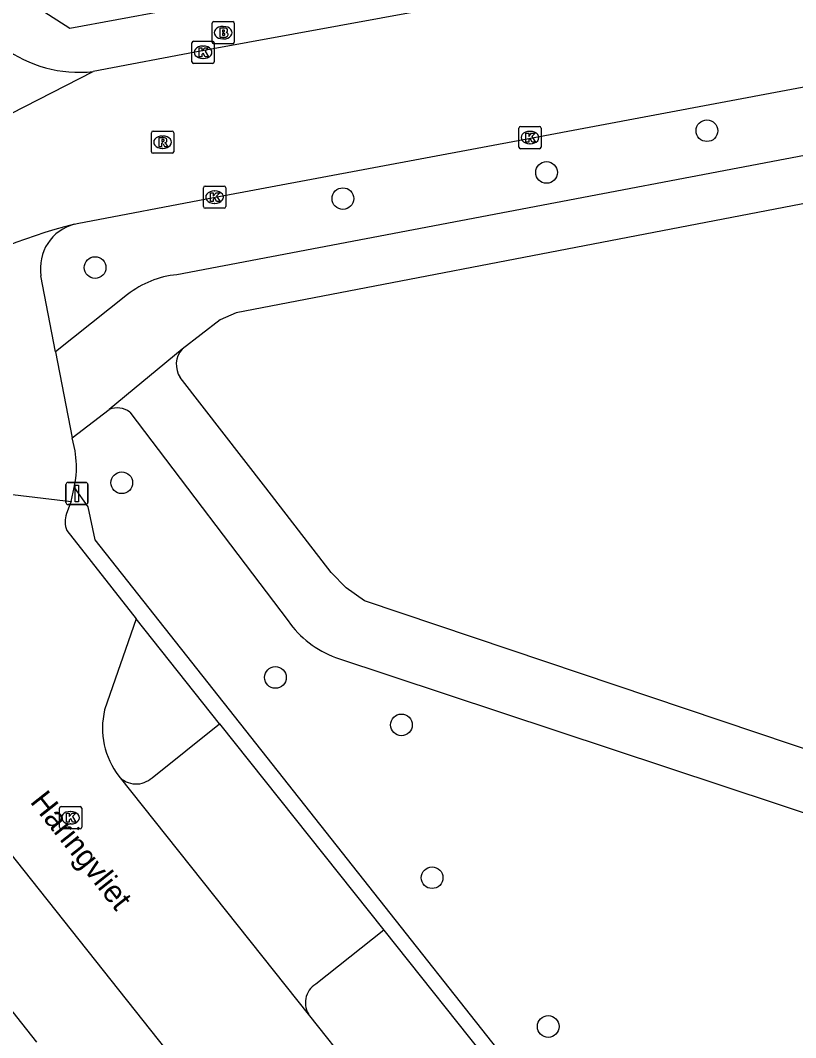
# Model space of a CAD drawing. Extents: x 157321 to 158827, y 386650 to 388532.
# Drawn here: x 157800.78 to 157835.71, y 387550.03 to 387595.87 of the extents above; entities that cross this region are included whole.
import ezdxf

# ---------------------------------------------------------------- set-up
doc = ezdxf.new("R2010")
doc.units = 0
for name, color, linetype in [('IMGEO_Boom', 7, 'Continuous'), ('IMGEO_Brandkraan', 7, 'Continuous'), ('IMGEO_Fietspad_open', 7, 'Continuous'), ('IMGEO_Haag', 7, 'Continuous'), ('IMGEO_Kolk', 7, 'Continuous'), ('IMGEO_Openbare_ruimte_label', 7, 'Continuous'), ('IMGEO_Pand', 7, 'Continuous'), ('IMGEO_Parkeervlak_open', 7, 'Continuous'), ('IMGEO_Rijbaan_lokaal_open', 7, 'Continuous'), ('IMGEO_Rioolput', 7, 'Continuous'), ('IMGEO_Verkeersbordpaal', 7, 'Continuous'), ('IMGEO_Voetpad_open', 7, 'Continuous')]:
    doc.layers.add(name, color=color, linetype=linetype)

msp = doc.modelspace()

# ---------------------------------------------------------------- linework, layer by layer
at = {"layer": 'IMGEO_Boom'}
for centre in [(157831.711, 387590.895), (157824.484, 387589.013), (157815.311, 387587.834), (157804.146, 387584.726), (157805.348, 387575.035), (157812.269, 387566.26), (157817.946, 387564.122), (157819.328, 387557.239), (157824.561, 387550.534)]:
    msp.add_circle(centre, 0.489, dxfattribs=at)
at = {"layer": 'IMGEO_Brandkraan'}
for p, q in [((157809.418, 387594.886), (157809.418, 387595.738)), ((157809.493, 387595.812), (157810.345, 387595.812)), ((157809.906, 387595.592), (157809.931, 387595.592)), ((157810.419, 387595.738), (157810.419, 387594.886)), ((157809.929, 387595.032), (157809.904, 387595.032)), ((157810.345, 387594.812), (157809.493, 387594.812))]:
    msp.add_line(p, q, dxfattribs=at)
for points in [[(157809.418, 387594.886), (157809.418, 387595.738)], [(157809.493, 387595.812), (157810.345, 387595.812)], [(157809.766, 387595.512), (157809.766, 387595.112), (157809.979, 387595.112)], [(157809.997, 387595.512), (157809.766, 387595.512)], [(157810.419, 387595.738), (157810.419, 387594.886)], [(157809.945, 387595.431), (157809.891, 387595.431), (157809.891, 387595.355)], [(157809.891, 387595.355), (157809.944, 387595.355)], [(157809.953, 387595.279), (157809.891, 387595.279), (157809.891, 387595.198)], [(157809.891, 387595.198), (157809.953, 387595.198)], [(157810.345, 387594.812), (157809.493, 387594.812)]]:
    msp.add_lwpolyline(points, dxfattribs=at)
for centre, radius, start, end in [((157809.495, 387595.736), 0.0765, 91.552, 178.448), ((157809.495, 387595.736), 0.0765, 91.552, 178.448), ((157810.001, 387595.367), 0.145, 59.4692, 91.5367), ((157810.026, 387595.414), 0.0922, 285.5137, 58.1501), ((157810.343, 387595.736), 0.0765, 1.552, 88.448), ((157810.343, 387595.736), 0.0765, 1.552, 88.448), ((157809.946, 387595.393), 0.0379, 267.8285, 90.9355), ((157809.954, 387595.238), 0.0404, 269.8759, 90.5077), ((157809.985, 387595.363), 0.251, 268.6676, 293.5347), ((157810.031, 387595.222), 0.105, 301.3115, 78.989), ((157809.495, 387594.888), 0.0765, 181.552, 268.448), ((157809.495, 387594.888), 0.0765, 181.552, 268.448), ((157810.343, 387594.888), 0.0765, 271.552, 358.448), ((157810.343, 387594.888), 0.0765, 271.552, 358.448)]:
    msp.add_arc(centre, radius, start, end, dxfattribs=at)
for centre, major_axis, ratio, start_param, end_param in [((157809.905, 387595.312), (-0.387, 0.002), 0.722429, 4.712389, 7.853982), ((157809.93, 387595.312), (-0.39, 0.002), 0.717154, 1.570796, 4.712389)]:
    msp.add_ellipse(centre, major_axis=major_axis, ratio=ratio, start_param=start_param, end_param=end_param, dxfattribs=at)
at = {"layer": 'IMGEO_Fietspad_open'}
for points in [[(157802.364, 387580.934), (157801.707, 387584.358)], [(157802.364, 387580.934), (157803.109, 387577.055)], [(157803.247, 387576.474), (157803.109, 387577.055)], [(157803.067, 387574.191), (157803.21, 387574.813)], [(157803.21, 387574.813), (157803.282, 387575.231)]]:
    msp.add_lwpolyline(points, dxfattribs=at)
for centre, radius, start, end in [((157803.747, 387584.69), 2.067, 104.6294, 189.2469), ((157798.269, 387575.712), 5.036, 354.5212, 8.7046)]:
    msp.add_arc(centre, radius, start, end, dxfattribs=at)
at = {"layer": 'IMGEO_Haag'}
for points in [[(157803.21, 387574.813), (157803.815, 387573.954), (157804.139, 387572.463), (157834.85, 387533.597)], [(157809.751, 387564.168), (157805.996, 387568.908)], [(157817.15, 387554.871), (157822.119, 387548.629)]]:
    msp.add_lwpolyline(points, dxfattribs=at)
at = {"layer": 'IMGEO_Kolk'}
for p, q in [((157808.51, 387594.002), (157808.51, 387594.854)), ((157808.585, 387594.928), (157809.437, 387594.928)), ((157808.998, 387594.708), (157809.023, 387594.708)), ((157809.511, 387594.854), (157809.511, 387594.002)), ((157809.021, 387594.148), (157808.996, 387594.148)), ((157809.437, 387593.928), (157808.585, 387593.928)), ((157823.237, 387590.158), (157823.237, 387591.01)), ((157823.312, 387591.084), (157824.164, 387591.084)), ((157823.725, 387590.864), (157823.75, 387590.864)), ((157824.238, 387591.01), (157824.238, 387590.158)), ((157824.164, 387590.084), (157823.312, 387590.084)), ((157823.748, 387590.304), (157823.723, 387590.304)), ((157809.029, 387587.475), (157809.029, 387588.327)), ((157809.104, 387588.401), (157809.956, 387588.401)), ((157809.517, 387588.181), (157809.542, 387588.181)), ((157810.03, 387588.327), (157810.03, 387587.475)), ((157809.956, 387587.401), (157809.104, 387587.401)), ((157809.54, 387587.621), (157809.515, 387587.621)), ((157802.541, 387559.514), (157802.541, 387560.366)), ((157802.616, 387560.44), (157803.468, 387560.44)), ((157803.029, 387560.22), (157803.054, 387560.22)), ((157803.542, 387560.366), (157803.542, 387559.514)), ((157803.468, 387559.44), (157802.616, 387559.44)), ((157803.052, 387559.66), (157803.027, 387559.66))]:
    msp.add_line(p, q, dxfattribs=at)
for points in [[(157808.51, 387594.002), (157808.51, 387594.854)], [(157808.585, 387594.928), (157809.437, 387594.928)], [(157808.831, 387594.628), (157808.954, 387594.628), (157808.954, 387594.477), (157809.084, 387594.628), (157809.248, 387594.628), (157809.102, 387594.477), (157809.255, 387594.228), (157809.103, 387594.228), (157809.018, 387594.392), (157808.954, 387594.325), (157808.954, 387594.228), (157808.831, 387594.228), (157808.831, 387594.628)], [(157809.511, 387594.854), (157809.511, 387594.002)], [(157809.437, 387593.928), (157808.585, 387593.928)], [(157823.237, 387590.158), (157823.237, 387591.01)], [(157823.312, 387591.084), (157824.164, 387591.084)], [(157824.238, 387591.01), (157824.238, 387590.158)], [(157823.558, 387590.784), (157823.681, 387590.784), (157823.681, 387590.633), (157823.811, 387590.784), (157823.975, 387590.784), (157823.829, 387590.633), (157823.982, 387590.384), (157823.83, 387590.384), (157823.745, 387590.548), (157823.681, 387590.481), (157823.681, 387590.384), (157823.558, 387590.384), (157823.558, 387590.784)], [(157824.164, 387590.084), (157823.312, 387590.084)], [(157809.029, 387587.475), (157809.029, 387588.327)], [(157809.104, 387588.401), (157809.956, 387588.401)], [(157810.03, 387588.327), (157810.03, 387587.475)], [(157809.35, 387588.101), (157809.473, 387588.101), (157809.473, 387587.95), (157809.603, 387588.101), (157809.767, 387588.101), (157809.621, 387587.95), (157809.774, 387587.701), (157809.622, 387587.701), (157809.537, 387587.865), (157809.473, 387587.798), (157809.473, 387587.701), (157809.35, 387587.701), (157809.35, 387588.101)], [(157809.956, 387587.401), (157809.104, 387587.401)], [(157802.541, 387559.514), (157802.541, 387560.366)], [(157802.616, 387560.44), (157803.468, 387560.44)], [(157803.542, 387560.366), (157803.542, 387559.514)], [(157802.862, 387560.14), (157802.985, 387560.14), (157802.985, 387559.989), (157803.115, 387560.14), (157803.279, 387560.14), (157803.133, 387559.989), (157803.286, 387559.74), (157803.134, 387559.74), (157803.049, 387559.904), (157802.985, 387559.837), (157802.985, 387559.74), (157802.862, 387559.74), (157802.862, 387560.14)], [(157803.468, 387559.44), (157802.616, 387559.44)]]:
    msp.add_lwpolyline(points, dxfattribs=at)
for centre, start, end in [((157808.587, 387594.852), 91.552, 178.448), ((157808.587, 387594.852), 91.552, 178.448), ((157809.435, 387594.852), 1.552, 88.448), ((157809.435, 387594.852), 1.552, 88.448), ((157808.587, 387594.004), 181.552, 268.448), ((157808.587, 387594.004), 181.552, 268.448), ((157809.435, 387594.004), 271.552, 358.448), ((157809.435, 387594.004), 271.552, 358.448), ((157823.314, 387591.008), 91.552, 178.448), ((157823.314, 387591.008), 91.552, 178.448), ((157824.162, 387591.008), 1.552, 88.448), ((157824.162, 387591.008), 1.552, 88.448), ((157823.314, 387590.16), 181.552, 268.448), ((157823.314, 387590.16), 181.552, 268.448), ((157824.162, 387590.16), 271.552, 358.448), ((157824.162, 387590.16), 271.552, 358.448), ((157809.106, 387588.325), 91.552, 178.448), ((157809.106, 387588.325), 91.552, 178.448), ((157809.954, 387588.325), 1.552, 88.448), ((157809.954, 387588.325), 1.552, 88.448), ((157809.106, 387587.477), 181.552, 268.448), ((157809.106, 387587.477), 181.552, 268.448), ((157809.954, 387587.477), 271.552, 358.448), ((157809.954, 387587.477), 271.552, 358.448), ((157802.618, 387560.364), 91.552, 178.448), ((157802.618, 387560.364), 91.552, 178.448), ((157803.466, 387560.364), 1.552, 88.448), ((157803.466, 387560.364), 1.552, 88.448), ((157802.618, 387559.516), 181.552, 268.448), ((157802.618, 387559.516), 181.552, 268.448), ((157803.466, 387559.516), 271.552, 358.448), ((157803.466, 387559.516), 271.552, 358.448)]:
    msp.add_arc(centre, 0.0765, start, end, dxfattribs=at)
for centre, major_axis, ratio, start_param, end_param in [((157808.997, 387594.428), (-0.387, 0.002), 0.722429, 4.712389, 7.853982), ((157809.022, 387594.428), (-0.39, 0.002), 0.717154, 1.570796, 4.712389), ((157823.724, 387590.584), (-0.387, 0.002), 0.722429, 4.712389, 7.853982), ((157823.749, 387590.584), (-0.39, 0.002), 0.717154, 1.570796, 4.712389), ((157809.516, 387587.901), (-0.387, 0.002), 0.722429, 4.712389, 7.853982), ((157809.541, 387587.901), (-0.39, 0.002), 0.717154, 1.570796, 4.712389), ((157803.028, 387559.94), (-0.387, 0.002), 0.722429, 4.712389, 7.853982), ((157803.053, 387559.94), (-0.39, 0.002), 0.717154, 1.570796, 4.712389)]:
    msp.add_ellipse(centre, major_axis=major_axis, ratio=ratio, start_param=start_param, end_param=end_param, dxfattribs=at)
at = {"layer": 'IMGEO_Pand'}
msp.add_lwpolyline([(157797.776, 387554.523), (157801.506, 387549.824)], dxfattribs=at)
at = {"layer": 'IMGEO_Parkeervlak_open'}
for points in [[(157806.713, 387561.742), (157809.751, 387564.168)], [(157809.751, 387564.168), (157817.15, 387554.871)], [(157817.15, 387554.871), (157814.089, 387552.441)]]:
    msp.add_lwpolyline(points, dxfattribs=at)
for centre, radius, start, end in [((157805.998, 387562.51), 1.049, 221.8551, 312.9398), ((157814.6, 387551.602), 0.982, 121.3478, 216.4662)]:
    msp.add_arc(centre, radius, start, end, dxfattribs=at)
at = {"layer": 'IMGEO_Rijbaan_lokaal_open'}
for points in [[(157847.531, 387601.774), (157838.502, 387600.061), (157823.212, 387597.114), (157808.967, 387594.489), (157804.065, 387593.562)], [(157803.225, 387586.69), (157803.34, 387586.71), (157809.483, 387587.888), (157823.694, 387590.55), (157837.996, 387593.239), (157850.039, 387595.554), (157853.29, 387595.423), (157855.571, 387595.37)], [(157792.988, 387587.904), (157804.065, 387593.562)], [(157800.167, 387574.541), (157803.067, 387574.191)], [(157803.067, 387574.191), (157803.031, 387574.082), (157802.855, 387573.642)], [(157802.873, 387572.88), (157805.996, 387568.908)], [(157805.996, 387568.908), (157804.575, 387564.795)], [(157829.287, 387521.854), (157827.412, 387524.212), (157792.348, 387568.39)], [(157805.217, 387561.81), (157813.81, 387551.018)], [(157813.81, 387551.018), (157817.616, 387546.205)]]:
    msp.add_lwpolyline(points, dxfattribs=at)
for centre, radius, start, end in [((157803.438, 387599.315), 5.787, 191.6206, 276.2197), ((157809.551, 387562.076), 25.414, 104.4143, 121.1402), ((157803.897, 387573.285), 1.102, 161.1115, 201.5949), ((157808.032, 387563.977), 3.553, 166.6902, 217.5858)]:
    msp.add_arc(centre, radius, start, end, dxfattribs=at)
at = {"layer": 'IMGEO_Rioolput'}
for p, q in [((157806.762, 387590.876), (157807.614, 387590.876)), ((157806.687, 387589.95), (157806.687, 387590.802)), ((157807.175, 387590.656), (157807.2, 387590.656)), ((157807.688, 387590.802), (157807.688, 387589.95)), ((157807.198, 387590.096), (157807.173, 387590.096)), ((157807.614, 387589.876), (157806.762, 387589.876))]:
    msp.add_line(p, q, dxfattribs=at)
for points in [[(157806.762, 387590.876), (157807.614, 387590.876)], [(157806.687, 387589.95), (157806.687, 387590.802)], [(157807.276, 387590.574), (157807.024, 387590.576), (157807.024, 387590.176)], [(157807.202, 387590.495), (157807.148, 387590.495), (157807.148, 387590.414)], [(157807.148, 387590.414), (157807.2, 387590.414)], [(157807.688, 387590.802), (157807.688, 387589.95)], [(157807.024, 387590.176), (157807.148, 387590.176), (157807.148, 387590.338), (157807.159, 387590.338)], [(157807.206, 387590.309), (157807.277, 387590.176), (157807.417, 387590.176), (157807.352, 387590.302)], [(157807.614, 387589.876), (157806.762, 387589.876)]]:
    msp.add_lwpolyline(points, dxfattribs=at)
for centre, radius, start, end in [((157806.764, 387590.8), 0.0765, 91.552, 178.448), ((157806.764, 387590.8), 0.0765, 91.552, 178.448), ((157807.612, 387590.8), 0.0765, 1.552, 88.448), ((157807.612, 387590.8), 0.0765, 1.552, 88.448), ((157807.184, 387590.603), 0.19, 274.7715, 282.9687), ((157807.208, 387590.399), 0.0964, 77.0061, 93.1865), ((157807.222, 387590.456), 0.0378, 276.6634, 79.6772), ((157807.275, 387590.464), 0.109, 350.3612, 89.416), ((157807.273, 387590.464), 0.112, 277.5842, 350.9817), ((157806.764, 387589.952), 0.0765, 181.552, 268.448), ((157806.764, 387589.952), 0.0765, 181.552, 268.448), ((157807.158, 387590.285), 0.0533, 26.0293, 88.6989), ((157807.257, 387590.249), 0.108, 29.5134, 73.7905), ((157807.612, 387589.952), 0.0765, 271.552, 358.448), ((157807.612, 387589.952), 0.0765, 271.552, 358.448)]:
    msp.add_arc(centre, radius, start, end, dxfattribs=at)
for centre, major_axis, ratio, start_param, end_param in [((157807.174, 387590.376), (-0.387, 0.002), 0.722429, 4.712389, 7.853982), ((157807.199, 387590.376), (-0.39, 0.002), 0.717154, 1.570796, 4.712389)]:
    msp.add_ellipse(centre, major_axis=major_axis, ratio=ratio, start_param=start_param, end_param=end_param, dxfattribs=at)
at = {"layer": 'IMGEO_Verkeersbordpaal'}
for p, q in [((157802.834, 387574.147), (157802.834, 387574.947)), ((157802.834, 387574.947), (157802.834, 387574.147)), ((157802.934, 387575.047), (157803.724, 387575.047)), ((157803.724, 387575.047), (157802.934, 387575.047)), ((157803.824, 387574.947), (157803.824, 387574.147)), ((157803.824, 387574.147), (157803.824, 387574.947)), ((157803.724, 387574.047), (157802.934, 387574.047)), ((157802.934, 387574.047), (157803.724, 387574.047))]:
    msp.add_line(p, q, dxfattribs=at)
msp.add_lwpolyline([(157803.254, 387574.922), (157803.404, 387574.922), (157803.404, 387574.172), (157803.254, 387574.172), (157803.254, 387574.922)], dxfattribs=at)
for centre, start, end in [((157802.934, 387574.947), 90, 180), ((157802.934, 387574.947), 90, 180), ((157803.724, 387574.947), 0, 90), ((157803.724, 387574.947), 360, 90), ((157802.934, 387574.147), 180, 270), ((157802.934, 387574.147), 180, 270), ((157803.724, 387574.147), 270, 0), ((157803.724, 387574.147), 270, 0)]:
    msp.add_arc(centre, 0.1, start, end, dxfattribs=at)
at = {"layer": 'IMGEO_Voetpad_open'}
for points in [[(157807.241, 387596.288), (157803.002, 387595.497), (157801.679, 387596.36), (157801.024, 387598.927), (157800.871, 387598.887)], [(157859.012, 387592.198), (157852.578, 387592.383), (157850.167, 387592.453), (157807.829, 387584.407)], [(157851.966, 387590.314), (157850.473, 387590.372), (157810.507, 387582.691), (157809.777, 387582.375), (157808.063, 387581.05)], [(157805.612, 387583.516), (157802.364, 387580.934)], [(157808.063, 387581.05), (157804.787, 387578.332)], [(157840.293, 387561.638), (157822.851, 387567.506), (157816.278, 387569.719), (157815.455, 387570.305), (157814.778, 387570.995), (157811.843, 387574.802), (157807.981, 387579.78)], [(157803.109, 387577.055), (157804.787, 387578.332)], [(157805.71, 387578.212), (157812.842, 387568.808)], [(157814.982, 387567.159), (157837.415, 387559.73)]]:
    msp.add_lwpolyline(points, dxfattribs=at)
for centre, radius, start, end in [((157808.256, 387580.141), 4.287, 95.7145, 128.0753), ((157808.838, 387580.362), 1.036, 138.4111, 214.2004), ((157805.145, 387577.476), 0.928, 52.5022, 112.6828), ((157816.566, 387571.427), 4.553, 215.1236, 249.6436)]:
    msp.add_arc(centre, radius, start, end, dxfattribs=at)

# ---------------------------------------------------------------- texts
at = {"layer": 'IMGEO_Openbare_ruimte_label'}
msp.add_text('Haringvliet', height=1, rotation=308.302, dxfattribs=at).set_placement((157801.186, 387560.651))

doc.saveas('drawing.dxf')
